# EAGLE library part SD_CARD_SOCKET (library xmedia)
SD/MMC Socket Media socket for SD and MMC cards. Push-push type. Schematic element and footprint production proven. Spark Fun Electronics SKU : PRT-00136
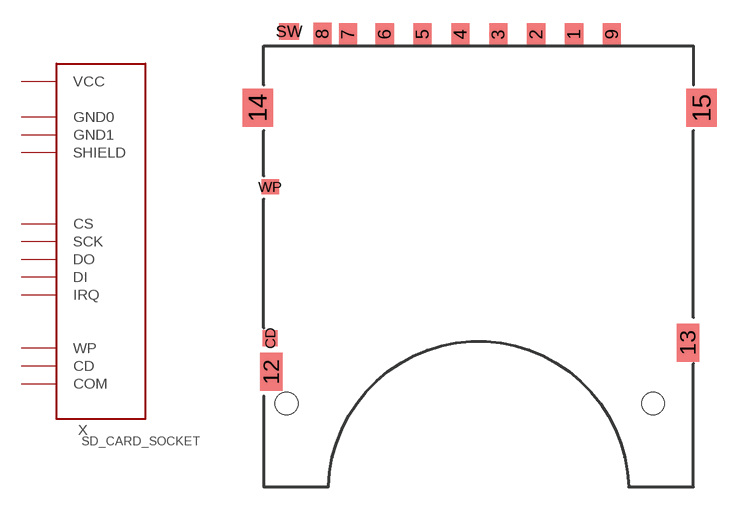
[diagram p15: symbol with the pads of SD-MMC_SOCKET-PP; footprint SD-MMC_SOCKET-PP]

Designator prefix X

## SD_CARD_SOCKETSD  [SD-MMC_SOCKET-PP]
1  CS  in
2  DI  in
3  GND0  sup
4  VCC  sup
5  SCK  in
6  GND1  sup
7  DO  out
8  IRQ
14  SHIELD
CD  CD
SW  COM
WP  WP

## Footprint SD-MMC_SOCKET-PP (pad centres in mm)
smd 1.2 x 1.5: 1 6.88,29.85; 2 4.38,29.85; 3 1.88,29.85; 4 -0.62,29.85; 5 -3.12,29.85; 6 -5.62,29.85; 7 -8.04,29.85; 8 -9.728,29.87; 9 9.38,29.85
smd 1.5 x 2.5: 12 -13.1,7.6; 13 14.402,9.525
smd 2 x 2.5: 14 -14,25; 15 15.3,25
smd 1 x 1.05: CD -13.18,9.8
smd 1.3 x 1.1: SW -11.938,30.048
smd 1.15 x 1: WP -13.18,19.8
hole 1.5 at -12.1,5.5
hole 1.5 at 12.1,5.5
